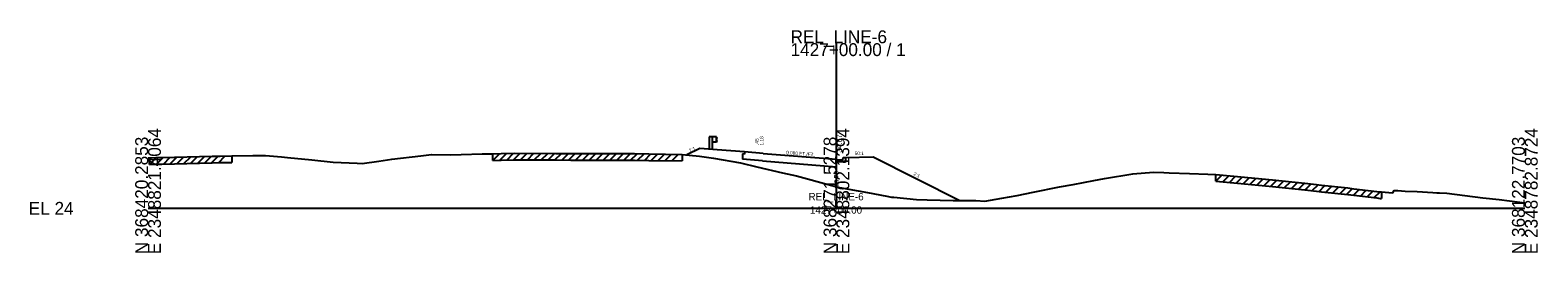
# Model space of a CAD drawing. Extents: x -26 to 403, y -10 to 6565.
# Drawn here: x -25.7 to 302.8, y 5990.3 to 6038.8 of the extents above; entities that cross this region are included whole.
import ezdxf

# ---------------------------------------------------------------- set-up
doc = ezdxf.new("R2010")
doc.units = 0
for name, color, linetype in [('RD_GPK_XS_Cell', 7, 'Continuous'), ('RD_XS_Base', 7, 'Continuous'), ('RD_XS_CurbBase', 7, 'Continuous'), ('RD_XS_CurbFront', 7, 'Continuous'), ('RD_XS_CurbTop', 7, 'Continuous'), ('RD_XS_EarthShd', 7, 'Continuous'), ('RD_XS_ExGround', 7, 'Continuous'), ('RD_XS_ExPaveRet', 7, 'Continuous'), ('RD_XS_GR', 7, 'Continuous'), ('RD_XS_Pave', 7, 'Continuous'), ('RD_XS_PaveShd', 7, 'Continuous'), ('RD_XS_TieSlope', 7, 'Continuous'), ('RD_XS_TX_Elev_EX', 7, 'Continuous'), ('RD_XS_TX_Elev_PR', 7, 'Continuous'), ('RD_XS_TX_Slope', 7, 'Continuous'), ('RD_XS_TX_Station', 7, 'Continuous'), ('RD_XS_TX_TOC', 7, 'Continuous')]:
    doc.layers.add(name, color=color, linetype=linetype)

msp = doc.modelspace()

# ---------------------------------------------------------------- linework, layer by layer
at = {"layer": 'RD_GPK_XS_Cell'}
for p, q in [((150, 6000), (150, 6035.96)), ((0, 6000), (150, 6000)), ((150, 6000), (300, 6000))]:
    msp.add_line(p, q, dxfattribs=at)
at = {"layer": 'RD_XS_Base'}
for p, q in [((130, 6012.27), (130, 6011.82)), ((130, 6011.82), (129.5, 6011.86)), ((129.5, 6011.86), (129.5, 6010.67)), ((133.87, 6010.32), (129.5, 6010.67)), ((133.87, 6010.32), (150, 6009.03))]:
    msp.add_line(p, q, dxfattribs=at)
at = {"layer": 'RD_XS_CurbBase'}
for p, q in [((151.5, 6010.07), (150, 6010.15)), ((150, 6009.03), (150, 6010.15)), ((152, 6010.07), (151.5, 6010.07)), ((152, 6011.07), (152, 6010.07))]:
    msp.add_line(p, q, dxfattribs=at)
at = {"layer": 'RD_XS_CurbFront'}
msp.add_line((150, 6010.15), (150, 6010.65), dxfattribs=at)
at = {"layer": 'RD_XS_CurbTop'}
for p, q in [((150, 6010.67), (150, 6010.65)), ((150, 6010.65), (151.41, 6010.57)), ((151.41, 6010.57), (151.5, 6011.07)), ((151.5, 6011.07), (152, 6011.07))]:
    msp.add_line(p, q, dxfattribs=at)
at = {"layer": 'RD_XS_EarthShd'}
for p, q in [((120.25, 6013.05), (117.42, 6011.64)), ((124, 6012.75), (120.25, 6013.05)), ((130, 6012.27), (124, 6012.75)), ((152, 6011.07), (158, 6011.19))]:
    msp.add_line(p, q, dxfattribs=at)
at = {"layer": 'RD_XS_ExGround'}
msp.add_lwpolyline([(0, 6011), (0.77, 6011.02), (1.72, 6011.05), (2.98, 6011.08), (13.94, 6011.35), (15.69, 6011.39), (18.24, 6011.42), (22.81, 6011.53), (25.56, 6011.48), (29.06, 6011.24), (30.42, 6011.05), (35.72, 6010.58), (40.34, 6010.06), (45.6, 6009.84), (46.63, 6009.79), (50.29, 6010.28), (53.11, 6010.69), (59.41, 6011.41), (61.79, 6011.71), (65.92, 6011.68), (68.21, 6011.71), (72.79, 6011.88), (75.15, 6011.87), (76.97, 6011.92), (79.78, 6011.99), (88.88, 6011.96), (92.13, 6011.95), (95.03, 6011.95), (105.98, 6011.91), (109.1, 6011.87), (116.39, 6011.75), (120.19, 6011.33), (123.23, 6010.96), (129.06, 6009.92), (132.68, 6009.07), (138.23, 6007.76), (141.27, 6007.06), (149, 6005), (150, 6004.7), (150.66, 6004.5), (156.77, 6003.42), (160.97, 6002.64), (162.03, 6002.43), (162.51, 6002.41), (167.43, 6001.9), (169.74, 6001.83), (175.46, 6001.74), (180.34, 6001.72), (182.31, 6001.59), (186.04, 6002.21), (189.38, 6002.82), (192.88, 6003.5), (198.64, 6004.7), (201.55, 6005.22), (206.09, 6006.04), (208.4, 6006.5), (214.58, 6007.49), (219.11, 6007.88), (221.34, 6007.79), (222.47, 6007.76), (226.91, 6007.58), (230.91, 6007.44), (232.67, 6007.36), (237.38, 6006.93), (245.04, 6006.22), (252.07, 6005.47), (254.59, 6005.2), (255.69, 6005.03), (261.45, 6004.45), (262.71, 6004.28), (267.73, 6003.7), (268.46, 6003.61), (268.79, 6003.58), (270.4, 6003.46), (271.24, 6003.4), (271.5, 6003.89), (271.84, 6003.87), (272.32, 6003.85), (273.94, 6003.73), (276.53, 6003.66), (279.93, 6003.47), (280.81, 6003.41), (281.4, 6003.39), (282.99, 6003.29), (290.85, 6002.28), (294.4, 6001.93), (298.92, 6001.37), (300, 6001.2)], dxfattribs=at)
at = {"layer": 'RD_XS_ExPaveRet'}
for p, q in [((0.33, 6009.57), (1.81, 6011.05)), ((0.33, 6009.57), (0.33, 6011.01)), ((0.33, 6009.57), (0.77, 6009.59)), ((0.77, 6009.59), (1.72, 6009.61)), ((1.72, 6009.61), (2.98, 6009.65)), ((1.83, 6009.62), (3.3, 6011.09)), ((2.98, 6009.65), (13.94, 6009.91)), ((3.33, 6009.65), (4.8, 6011.13)), ((4.83, 6009.69), (6.3, 6011.16)), ((6.33, 6009.73), (7.8, 6011.2)), ((7.83, 6009.76), (9.3, 6011.24)), ((9.33, 6009.8), (10.8, 6011.27)), ((10.83, 6009.84), (12.3, 6011.31)), ((12.33, 6009.87), (13.8, 6011.34)), ((13.83, 6009.91), (15.3, 6011.38)), ((13.94, 6009.91), (15.69, 6009.95)), ((15.33, 6009.94), (16.79, 6011.4)), ((15.69, 6009.95), (18.24, 6009.98)), ((18.24, 6011.42), (18.24, 6009.98)), ((75.15, 6010.44), (76.63, 6011.91)), ((75.15, 6010.44), (75.15, 6011.87)), ((75.15, 6010.44), (76.97, 6010.48)), ((76.65, 6010.47), (78.13, 6011.95)), ((76.97, 6010.48), (79.78, 6010.55)), ((78.15, 6010.51), (79.63, 6011.98)), ((79.65, 6010.55), (81.09, 6011.98)), ((79.78, 6010.55), (88.88, 6010.53)), ((81.15, 6010.55), (82.59, 6011.98)), ((82.65, 6010.54), (84.09, 6011.98)), ((84.15, 6010.54), (85.59, 6011.97)), ((85.65, 6010.53), (87.09, 6011.97)), ((87.15, 6010.53), (88.59, 6011.96)), ((88.65, 6010.53), (90.09, 6011.96)), ((88.88, 6010.53), (92.13, 6010.52)), ((90.15, 6010.52), (91.59, 6011.96)), ((91.65, 6010.52), (93.09, 6011.95)), ((92.13, 6010.52), (95.03, 6010.51)), ((93.15, 6010.51), (94.59, 6011.95)), ((94.65, 6010.51), (96.09, 6011.94)), ((95.03, 6010.51), (105.98, 6010.47)), ((96.15, 6010.5), (97.59, 6011.94)), ((97.65, 6010.5), (99.09, 6011.93)), ((99.15, 6010.5), (100.59, 6011.93)), ((100.65, 6010.49), (102.09, 6011.92)), ((102.15, 6010.49), (103.59, 6011.92)), ((103.65, 6010.48), (105.09, 6011.91)), ((105.15, 6010.48), (106.58, 6011.9)), ((105.98, 6010.47), (109.1, 6010.43)), ((106.65, 6010.46), (108.07, 6011.88)), ((108.15, 6010.44), (109.57, 6011.86)), ((109.1, 6010.43), (116.39, 6010.32)), ((109.65, 6010.42), (111.07, 6011.84)), ((111.15, 6010.4), (112.57, 6011.81)), ((112.65, 6010.38), (114.07, 6011.79)), ((114.15, 6010.35), (115.57, 6011.77)), ((116.39, 6011.75), (116.39, 6010.32)), ((232.67, 6005.93), (232.67, 6007.36)), ((232.67, 6005.93), (233.99, 6007.24)), ((232.67, 6005.93), (237.38, 6005.5)), ((234.17, 6005.79), (235.49, 6007.11)), ((235.67, 6005.65), (236.99, 6006.97)), ((237.17, 6005.52), (238.48, 6006.83)), ((238.67, 6005.38), (239.98, 6006.69)), ((240.17, 6005.24), (241.48, 6006.55)), ((241.67, 6005.1), (242.98, 6006.41)), ((243.17, 6004.96), (244.48, 6006.27)), ((244.67, 6004.82), (245.97, 6006.12)), ((246.17, 6004.66), (247.47, 6005.96)), ((247.67, 6004.5), (248.97, 6005.8)), ((249.17, 6004.34), (250.47, 6005.64)), ((237.38, 6005.5), (245.04, 6004.78)), ((245.04, 6004.78), (252.07, 6004.03)), ((250.67, 6004.18), (251.97, 6005.48)), ((252.07, 6004.03), (254.59, 6003.76)), ((252.17, 6004.02), (253.47, 6005.32)), ((253.67, 6003.86), (254.95, 6005.14)), ((254.59, 6003.76), (255.69, 6003.59)), ((255.17, 6003.67), (256.45, 6004.95)), ((255.69, 6003.59), (261.45, 6003.01)), ((256.67, 6003.49), (257.97, 6004.8)), ((258.17, 6003.34), (259.47, 6004.65)), ((259.67, 6003.19), (260.97, 6004.49)), ((261.17, 6003.04), (262.45, 6004.31)), ((261.45, 6003.01), (262.71, 6002.84)), ((262.67, 6002.85), (263.96, 6004.14)), ((262.71, 6002.84), (267.73, 6002.27)), ((264.17, 6002.68), (265.46, 6003.96)), ((265.67, 6002.5), (266.96, 6003.79)), ((267.17, 6002.33), (268.45, 6003.61)), ((268.79, 6003.58), (268.79, 6002.15)), ((267.73, 6002.27), (268.46, 6002.17)), ((268.46, 6002.17), (268.79, 6002.15))]:
    msp.add_line(p, q, dxfattribs=at)
at = {"layer": 'RD_XS_GR'}
for p, q in [((122.91, 6015.58), (122.25, 6015.58)), ((122.25, 6015.58), (122.25, 6012.89)), ((123.83, 6015.58), (122.91, 6015.58)), ((122.91, 6015.58), (122.91, 6012.84)), ((123.83, 6014.41), (123.83, 6015.58)), ((123.83, 6015.51), (124, 6015.31)), ((123.83, 6014.41), (122.91, 6014.41)), ((124, 6015.26), (123.83, 6015.06)), ((124, 6014.74), (123.83, 6014.94)), ((123.83, 6014.49), (124, 6014.69)), ((124, 6015.31), (124, 6015.26)), ((124, 6014.69), (124, 6014.74))]:
    msp.add_line(p, q, dxfattribs=at)
at = {"layer": 'RD_XS_Pave'}
msp.add_line((134, 6011.95), (150, 6010.67), dxfattribs=at)
at = {"layer": 'RD_XS_PaveShd'}
msp.add_line((134, 6011.95), (130, 6012.27), dxfattribs=at)
at = {"layer": 'RD_XS_TieSlope'}
msp.add_line((158, 6011.19), (176.91, 6001.73), dxfattribs=at)

# ---------------------------------------------------------------- texts
at = {"layer": 'RD_GPK_XS_Cell'}
for s, p in [('REL_LINE-6', (140, 6035.96)), ('1427+00.00 / 1', (140, 6033.16)), ('EL 24', (-26, 5998.6))]:
    msp.add_text(s, height=2.8, dxfattribs=at).set_placement(p)
for s, p in [('N 368420.2853', (0, 5990)), ('E 2348821.4064', (2.8, 5990)), ('N 368271.5278', (150, 5990)), ('E 2348802.1394', (152.8, 5990)), ('N 368122.7703', (300, 5990)), ('E 2348782.8724', (302.8, 5990))]:
    msp.add_text(s, height=2.8, rotation=90, dxfattribs=at).set_placement(p)
at = {"layer": 'RD_XS_Base'}
for s, p in [('1.18', (134.06, 6013.68)), ('.45', (133.02, 6013.8))]:
    msp.add_text(s, height=0.75, rotation=90, dxfattribs=at).set_placement(p)
at = {"layer": 'RD_XS_TX_Elev_EX'}
msp.add_text('28.70', height=1, rotation=90, dxfattribs=at).set_placement((150.5, 6004.7))
at = {"layer": 'RD_XS_TX_Elev_PR'}
msp.add_text('34.67', height=1.2, rotation=90, dxfattribs=at).set_placement((151.2, 6012.1))
at = {"layer": 'RD_XS_TX_Slope'}
for s, rotation, p in [('2:1', 26.5651, (118.09, 6012.18)), ('0.080 FT./FT.', 355.4261, (139, 6011.8)), ('50:1', 1.1458, (153.97, 6011.59)), ('2:1', 333.4349, (166.71, 6007.27))]:
    msp.add_text(s, height=0.75, rotation=rotation, dxfattribs=at).set_placement(p)
at = {"layer": 'RD_XS_TX_Station'}
for s, p in [('REL_LINE-6', (143.92, 6001.74)), ('1427+00.00', (144.23, 5998.84))]:
    msp.add_text(s, height=1.6, dxfattribs=at).set_placement(p)
at = {"layer": 'RD_XS_TX_TOC'}
msp.add_text('TOCRT', height=0.05, dxfattribs=at).set_placement((151.21, 6011.02))

doc.saveas('drawing.dxf')
